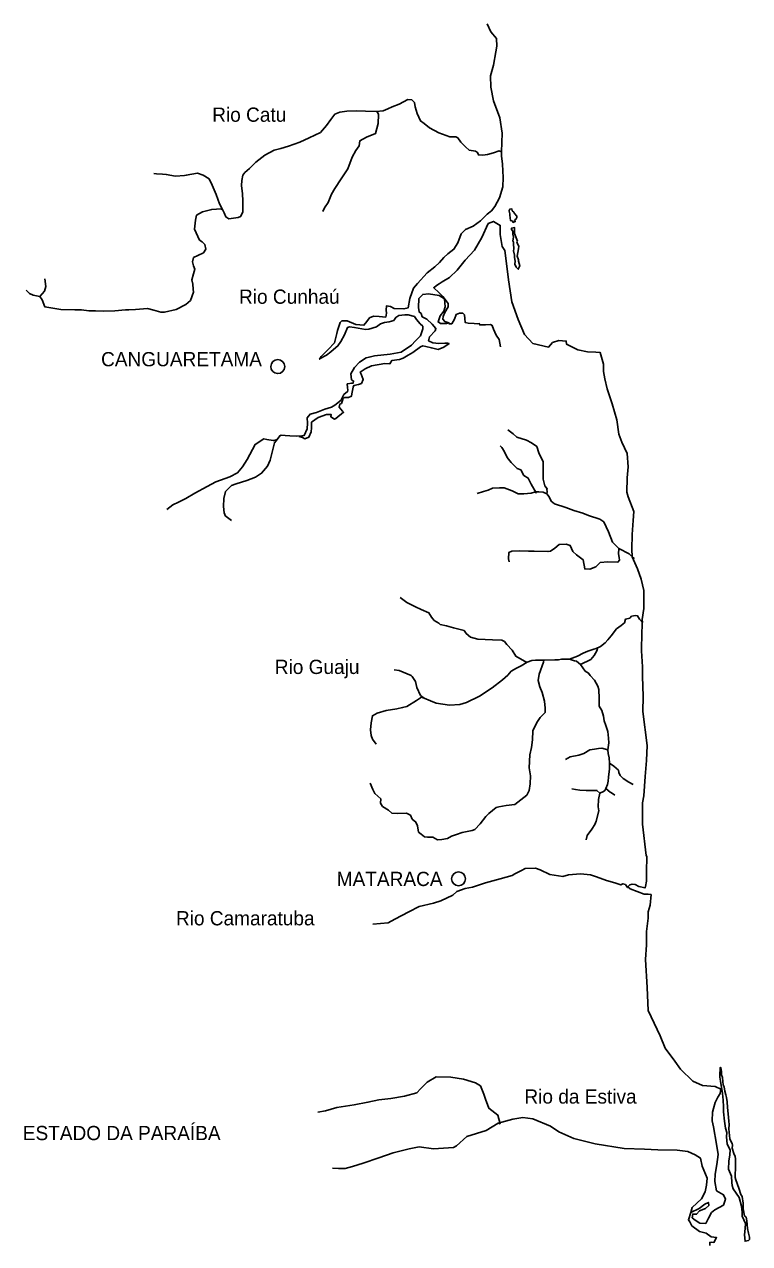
# Model space of a CAD drawing. Extents: x 662444 to 1640468, y 7452018 to 9606170.
# Drawn here: x 1584655 to 1619732, y 9241680 to 9300665 of the extents above; entities that cross this region are included whole.
import ezdxf

# ---------------------------------------------------------------- set-up
doc = ezdxf.new("R2010")
doc.units = 0
for name, color, linetype in [('Level 1', 7, 'Continuous'), ('Level 2', 7, 'Continuous'), ('Level 3', 7, 'Continuous')]:
    doc.layers.add(name, color=color, linetype=linetype)

msp = doc.modelspace()

# ---------------------------------------------------------------- linework, layer by layer
at = {"layer": 'Level 1'}
for points in [[(1607340, 9298700), (1607454, 9299341), (1607511, 9299617), (1607497, 9299976), (1607214, 9300309), (1607039, 9300696)], [(1599983, 9282492), (1600026, 9282597), (1600111, 9282757), (1600286, 9282899), (1600304, 9282964), (1600275, 9283095), (1600272, 9283275), (1600304, 9283282), (1600476, 9283302), (1600564, 9283308), (1600575, 9283406), (1600480, 9283474), (1600439, 9283752), (1600618, 9284072), (1600868, 9284327), (1601182, 9284531), (1601329, 9284568), (1601590, 9284626), (1602347, 9284712), (1602876, 9284813), (1603379, 9285150), (1603579, 9285349), (1603806, 9285604), (1603920, 9285935), (1603931, 9286058), (1603798, 9286175), (1603626, 9286391), (1603516, 9286540), (1603218, 9286606), (1603064, 9286610), (1602764, 9286584), (1602622, 9286490), (1602522, 9286337), (1602293, 9286270), (1602065, 9286244), (1601877, 9286184), (1601686, 9286026), (1601310, 9285913), (1601148, 9285908), (1600623, 9285996), (1600381, 9286026), (1600283, 9286005), (1600136, 9285650), (1599957, 9285328), (1599821, 9285111), (1599613, 9284929), (1599472, 9284828), (1599266, 9284670), (1598962, 9284499), (1598936, 9284466), (1599004, 9284595), (1599354, 9284944), (1599655, 9285263), (1599773, 9285716), (1599801, 9285862), (1599934, 9286249), (1600016, 9286321), (1600260, 9286331), (1600685, 9286149), (1601080, 9286106), (1601224, 9286297), (1601350, 9286466), (1601547, 9286543), (1601822, 9286535), (1602129, 9286503), (1602167, 9286698), (1602154, 9286844), (1602168, 9287048), (1602362, 9287011), (1602545, 9286916), (1603015, 9286896), (1603220, 9286956), (1603297, 9287402), (1603473, 9287903), (1603666, 9288135), (1604134, 9288644), (1604515, 9288935), (1604731, 9289142), (1604940, 9289381), (1605132, 9289563), (1605430, 9289784), (1605625, 9290089), (1605783, 9290525), (1605992, 9290748), (1606353, 9290909), (1606716, 9291169), (1607041, 9291478), (1607241, 9291645), (1607409, 9291861), (1607640, 9292270), (1607791, 9292804), (1607813, 9293260), (1607774, 9293905), (1607728, 9294306), (1607725, 9294501), (1607758, 9295405), (1607658, 9296141), (1607348, 9296963), (1607213, 9297636), (1607204, 9298174), (1607340, 9298700)], [(1607725, 9294501), (1607614, 9294553), (1607343, 9294446), (1607049, 9294364), (1606829, 9294345), (1606619, 9294350), (1606573, 9294473), (1606478, 9294533), (1606171, 9294574), (1605989, 9294741), (1605769, 9294967), (1605612, 9295183), (1605524, 9295226), (1605234, 9295233), (1604695, 9295418), (1604256, 9295666), (1603995, 9295868), (1603812, 9295994), (1603659, 9296357), (1603554, 9296669), (1603520, 9296891), (1603394, 9297023), (1603208, 9297028), (1602780, 9296803), (1602444, 9296673), (1602230, 9296573), (1602002, 9296489), (1601668, 9296457), (1601158, 9296469), (1600697, 9296481), (1600251, 9296468), (1599916, 9296412), (1599678, 9296328), (1599469, 9296065), (1599266, 9295776), (1598973, 9295441), (1598423, 9295170), (1597979, 9294970), (1597423, 9294779), (1597055, 9294659), (1596729, 9294585), (1596285, 9294344), (1595845, 9293997), (1595545, 9293686), (1595322, 9293505), (1595221, 9293377), (1595173, 9293118), (1595158, 9292873), (1595212, 9292473), (1595227, 9292130), (1595228, 9291870), (1595220, 9291585), (1595109, 9291367), (1595002, 9291329), (1594538, 9291252), (1594404, 9291353), (1594320, 9291543), (1594251, 9291682), (1594097, 9291988), (1593923, 9292432), (1593732, 9292885), (1593587, 9293191), (1593308, 9293369), (1593027, 9293465), (1592482, 9293365), (1592392, 9293351), (1591970, 9293329), (1591518, 9293406), (1591332, 9293411), (1591050, 9293434), (1590912, 9293454)], [(1601668, 9296457), (1601717, 9296455), (1601777, 9296307), (1601773, 9295875), (1601630, 9295381), (1601204, 9295213), (1600883, 9295034), (1600852, 9294782), (1600691, 9294558), (1600504, 9294237), (1600295, 9293680), (1599973, 9293191), (1599668, 9292719), (1599515, 9292454), (1599350, 9292050), (1599164, 9291786), (1599094, 9291617)], [(1594251, 9291682), (1594171, 9291742), (1593717, 9291713), (1593268, 9291593), (1592979, 9291429), (1592932, 9291195), (1592888, 9290756), (1593125, 9290228), (1593260, 9290152), (1593378, 9290010), (1593429, 9289797), (1593310, 9289621), (1593039, 9289489), (1592841, 9289380), (1592787, 9289178), (1592831, 9288982), (1592891, 9288817), (1592827, 9288590), (1592755, 9288308), (1592806, 9288094), (1592816, 9287858), (1592827, 9287710), (1592687, 9287315), (1592462, 9287109), (1592002, 9286868), (1591424, 9286744), (1591253, 9286749), (1590908, 9286847), (1590610, 9286928), (1590033, 9286870), (1589709, 9286854), (1589539, 9286858), (1589035, 9286814), (1588468, 9286786), (1588095, 9286805), (1587771, 9286813), (1587424, 9286855), (1587093, 9286863), (1586421, 9286879), (1585639, 9287005), (1585519, 9287342), (1585409, 9287508), (1585087, 9287566), (1584903, 9287651), (1584737, 9287810)], [(1608127, 9291443), (1608129, 9291508), (1608108, 9291630), (1608101, 9291663), (1608134, 9291720), (1608233, 9291741), (1608254, 9291651), (1608333, 9291576), (1608356, 9291510), (1608466, 9291386), (1608471, 9291319), (1608446, 9291255), (1608379, 9291208), (1608394, 9291127), (1608287, 9291088), (1608281, 9291146), (1608160, 9291180), (1608127, 9291443)], [(1618130, 9246499), (1617993, 9247327), (1617920, 9247621), (1617932, 9248045), (1617987, 9248223), (1618068, 9248514), (1618197, 9248764), (1618315, 9248948), (1618346, 9249151), (1618058, 9249281), (1617459, 9249330), (1616980, 9249546), (1616397, 9250125), (1616116, 9250507), (1615649, 9251132), (1615406, 9251733), (1614819, 9252964), (1614778, 9254074), (1614696, 9255420), (1614749, 9256129), (1614743, 9256772), (1614827, 9257423), (1614820, 9257733), (1614926, 9258056), (1614965, 9258569), (1614820, 9258581), (1614698, 9258584), (1614634, 9258586), (1613952, 9258840), (1613849, 9258933), (1613941, 9259044), (1614056, 9259073), (1614201, 9259061), (1614376, 9258959), (1614675, 9258886), (1614693, 9258959), (1614741, 9259210), (1614745, 9259667), (1614767, 9260408), (1614736, 9260457), (1614545, 9261979), (1614558, 9262998), (1614617, 9263338), (1614676, 9264283), (1614739, 9265047), (1614784, 9265771), (1614563, 9267424), (1614585, 9268149), (1614548, 9269137), (1614553, 9269584), (1614510, 9270361), (1614511, 9271265), (1614528, 9271551), (1614537, 9271876), (1614617, 9272412), (1614610, 9273276), (1614479, 9273826), (1614307, 9274319), (1614056, 9274905), (1614042, 9275280), (1614055, 9275989), (1614106, 9276656), (1614134, 9277104), (1613863, 9277812), (1613789, 9278042), (1613808, 9278727), (1613856, 9279255), (1613809, 9279900), (1613549, 9280453), (1613414, 9280848), (1613312, 9281528), (1613090, 9282308), (1612844, 9283039), (1612728, 9283523), (1612665, 9283876), (1612659, 9284234), (1612505, 9284785), (1612302, 9284806), (1611896, 9284817), (1611421, 9284918), (1610878, 9285194), (1610865, 9285340), (1610510, 9285374), (1610199, 9285268), (1609998, 9285045), (1609249, 9285228), (1608849, 9285661), (1608537, 9286395), (1608236, 9287242), (1608064, 9288314), (1607973, 9289100), (1607885, 9289721), (1607768, 9289920), (1607663, 9290493), (1607667, 9290941), (1607508, 9291035), (1607340, 9291137), (1607093, 9291029), (1606775, 9290361), (1606418, 9289750), (1605967, 9289265)], [(1608513, 9290178), (1608480, 9290146), (1608510, 9290047), (1608572, 9289931), (1608559, 9289810), (1608514, 9289623), (1608492, 9289444), (1608553, 9289280), (1608551, 9289215), (1608625, 9288977), (1608540, 9288816), (1608437, 9288917), (1608376, 9289065), (1608389, 9289203), (1608361, 9289383), (1608364, 9289497), (1608313, 9289710), (1608324, 9289808), (1608306, 9290044), (1608317, 9290133), (1608278, 9290191), (1608308, 9290378), (1608287, 9290509), (1608283, 9290656), (1608213, 9290747), (1608214, 9290804), (1608361, 9290833), (1608358, 9290735), (1608353, 9290548), (1608513, 9290178)], [(1605967, 9289265), (1605589, 9288778), (1605213, 9288412), (1604867, 9288217), (1604719, 9288115), (1604595, 9288037), (1604454, 9287926), (1604698, 9287692), (1604896, 9287499), (1605052, 9287284), (1605154, 9287166), (1605150, 9286996), (1604987, 9286723), (1604917, 9286529), (1604898, 9286399), (1604983, 9286291), (1605177, 9286229), (1605078, 9286190), (1604786, 9286198), (1604668, 9286275), (1604772, 9286558), (1604941, 9286789), (1605004, 9287008), (1604975, 9287391), (1604719, 9287553), (1604203, 9287624), (1603926, 9287605), (1603734, 9287399), (1603714, 9286975), (1603748, 9286755), (1603852, 9286671), (1603896, 9286523), (1604112, 9286411), (1604372, 9286160), (1604561, 9285951), (1604518, 9285839), (1604241, 9285544), (1604204, 9285358), (1604404, 9285255), (1604694, 9285222), (1604987, 9285239), (1605133, 9285236), (1605198, 9285234), (1604941, 9285054), (1604671, 9284930), (1604340, 9285011), (1604066, 9285084), (1603922, 9285113), (1603806, 9285067), (1603443, 9284799), (1603213, 9284666), (1602981, 9284525), (1602793, 9284457), (1602435, 9284409), (1602333, 9284248), (1602083, 9284255), (1601440, 9284150), (1601144, 9284002), (1600896, 9283845), (1600950, 9283738), (1601048, 9283491), (1600954, 9283298), (1600815, 9283245), (1600594, 9283201), (1600552, 9283113), (1600494, 9282797), (1600483, 9282682), (1600326, 9282614), (1600148, 9282618), (1600074, 9282587), (1600064, 9282514), (1599986, 9282328), (1599905, 9282290), (1599894, 9282234), (1599884, 9282144), (1600049, 9281960), (1600096, 9281902), (1599723, 9281594), (1599657, 9281572), (1599482, 9281674), (1599485, 9281796), (1599404, 9281798), (1599274, 9281784), (1598857, 9281641), (1598543, 9281421), (1598543, 9281152), (1598530, 9280948), (1598417, 9280690), (1598221, 9280622), (1598100, 9280674), (1597948, 9280735), (1598192, 9280778), (1598339, 9281100), (1598355, 9281377), (1598338, 9281638), (1598473, 9281806), (1598791, 9281895), (1599185, 9282048), (1599503, 9282154), (1599668, 9282247), (1599983, 9282492)], [(1585409, 9287508), (1585635, 9287763), (1585698, 9287989), (1585636, 9288357)], [(1605177, 9286229), (1605199, 9286180), (1605329, 9286176), (1605457, 9286410), (1605536, 9286627), (1605700, 9286688), (1605863, 9286692), (1605949, 9286609), (1605952, 9286429), (1605971, 9286249), (1606124, 9286205), (1606416, 9286189), (1606554, 9286185), (1606659, 9286191), (1606674, 9286158), (1606682, 9286125), (1606957, 9286135), (1607201, 9286144), (1607281, 9286101), (1607340, 9285913), (1607478, 9285624), (1607626, 9285425), (1607681, 9285064)], [(1598192, 9280778), (1598071, 9280764), (1597803, 9280747), (1597487, 9280755), (1597260, 9280778), (1597074, 9280790), (1597009, 9280759), (1596875, 9280583), (1596756, 9280416), (1596667, 9280092), (1596539, 9279582), (1596417, 9279292), (1596131, 9278949), (1595827, 9278761), (1595409, 9278593), (1594903, 9278442), (1594673, 9278359), (1594390, 9278065), (1594307, 9277725), (1594280, 9277335), (1594321, 9277040), (1594388, 9276876), (1594420, 9276851), (1594675, 9276664)], [(1609927, 9277947), (1609948, 9278061), (1609926, 9278159), (1609943, 9278191), (1609825, 9278333), (1609745, 9278661), (1609745, 9278931), (1609751, 9279151), (1609745, 9279501), (1609539, 9279938), (1609434, 9280242), (1609188, 9280420), (1608940, 9280548), (1608473, 9280691), (1608300, 9280858), (1608038, 9281045)], [(1596875, 9280583), (1596792, 9280553), (1596727, 9280539), (1596695, 9280540), (1596389, 9280588), (1596236, 9280616), (1595815, 9280342), (1595429, 9279610), (1595209, 9279258), (1594958, 9278963), (1594596, 9278776), (1593917, 9278533), (1593489, 9278316), (1592897, 9277981), (1592469, 9277723), (1592107, 9277545), (1591829, 9277422), (1591546, 9277193)], [(1609371, 9278043), (1609403, 9278002), (1609171, 9278415), (1609026, 9278712), (1608819, 9278848), (1608665, 9279114), (1608487, 9279175), (1608195, 9279467), (1608000, 9279717), (1607863, 9280014), (1607746, 9280197), (1607660, 9280273)], [(1614056, 9274905), (1614143, 9274829), (1613914, 9275056), (1613411, 9275305), (1613104, 9275614), (1612900, 9276117), (1612678, 9276604), (1612487, 9276723), (1611941, 9276908), (1611669, 9277021), (1611227, 9277147), (1610850, 9277288), (1610287, 9277473), (1610128, 9277592), (1610029, 9277815), (1609927, 9277947), (1609752, 9278034), (1609542, 9278056), (1609371, 9278043), (1609159, 9277984), (1608810, 9277960), (1608542, 9277959), (1608255, 9278097), (1607861, 9278238), (1607635, 9278252), (1607302, 9278220), (1607080, 9278136), (1606860, 9278060), (1606549, 9277962)], [(1613411, 9275305), (1613402, 9275297), (1613396, 9275053), (1613423, 9274880), (1613436, 9274750), (1613360, 9274654), (1612874, 9274659), (1612508, 9274628), (1612300, 9274429), (1611997, 9274315), (1611762, 9274321), (1611677, 9274763), (1611351, 9275000), (1611178, 9275160), (1611057, 9275448), (1610856, 9275526), (1610515, 9275503), (1610316, 9275329), (1610101, 9275180), (1609979, 9275159), (1609307, 9275176), (1609040, 9275183), (1608618, 9275202), (1608237, 9275188), (1608080, 9275110), (1608064, 9274817), (1608101, 9274662)], [(1608975, 9269805), (1608950, 9269790), (1608424, 9270096), (1608255, 9270386), (1607986, 9270662), (1607869, 9270812), (1607749, 9270881), (1607296, 9270892), (1606585, 9270928), (1606239, 9271026), (1606025, 9271203), (1605924, 9271336), (1605417, 9271472), (1605071, 9271570), (1604766, 9271635), (1604702, 9271701), (1604478, 9271822), (1604346, 9271980), (1604222, 9272196), (1603854, 9272351), (1603574, 9272481), (1603159, 9272704), (1602833, 9272941)], [(1614537, 9271876), (1614550, 9271729), (1614400, 9271896), (1614316, 9272045), (1614210, 9272064), (1614023, 9272028), (1613932, 9271941), (1613735, 9271897), (1613673, 9271719), (1613524, 9271584), (1613292, 9271419), (1613032, 9271084), (1612872, 9270884), (1612738, 9270749), (1612522, 9270576), (1612309, 9270476), (1612203, 9270445), (1611908, 9270339), (1611678, 9270247), (1611407, 9270100), (1611022, 9269963)], [(1612309, 9270476), (1612383, 9270506), (1612382, 9270473), (1612338, 9270361), (1612218, 9270135), (1612050, 9269937), (1611558, 9269705)], [(1609782, 9269907), (1609762, 9269817), (1609550, 9269235), (1609501, 9268928), (1609581, 9268615), (1609695, 9268343), (1609814, 9267925), (1609844, 9267590), (1609837, 9267377), (1609605, 9267140), (1609444, 9266891), (1609245, 9266480), (1609233, 9266057), (1609181, 9265683), (1609107, 9265327), (1609072, 9264692), (1609134, 9264307), (1609122, 9263916), (1609074, 9263607), (1608953, 9263374), (1608374, 9262926), (1607951, 9262871), (1607608, 9262815), (1607478, 9262777), (1607113, 9262494), (1606971, 9262343), (1606694, 9261992), (1606434, 9261713), (1606320, 9261667), (1605823, 9261575), (1605553, 9261476), (1605308, 9261392), (1605126, 9261276), (1604841, 9261225), (1604629, 9261215), (1604415, 9261343), (1604147, 9261350), (1604003, 9261362), (1603844, 9261488), (1603718, 9261589), (1603661, 9261884), (1603594, 9262073), (1603411, 9262217), (1603328, 9262406), (1603136, 9262510), (1602690, 9262496), (1602431, 9262504), (1602273, 9262646), (1601978, 9262833), (1601886, 9262991), (1601892, 9263203), (1601600, 9263454), (1601516, 9263652), (1601387, 9263957)], [(1602540, 9269436), (1602782, 9269413), (1603358, 9269170), (1603413, 9269112), (1603577, 9268871), (1603642, 9268592), (1603808, 9268205), (1603991, 9268070), (1604296, 9267932), (1604568, 9267826), (1605213, 9267736), (1605717, 9267763), (1606035, 9267861), (1606660, 9268163), (1607287, 9268570), (1607776, 9268957), (1608033, 9269178), (1608201, 9269369), (1608456, 9269517), (1608687, 9269625), (1608975, 9269805), (1609205, 9269889), (1609375, 9269909), (1609780, 9269907), (1610316, 9269916), (1610486, 9269928), (1610641, 9269949), (1611022, 9269963), (1611263, 9269867), (1611351, 9269865), (1611558, 9269705), (1611783, 9269373), (1611943, 9269279), (1612028, 9269162), (1612224, 9268945), (1612395, 9268655), (1612447, 9268492), (1612450, 9268059), (1612456, 9267675), (1612580, 9267468), (1612661, 9267205), (1612704, 9266976), (1612770, 9266754), (1612874, 9266450), (1612906, 9266139), (1612924, 9265911), (1612882, 9265562), (1612884, 9265390), (1612935, 9265177), (1612960, 9264924), (1612952, 9264646), (1612908, 9264240), (1612895, 9264045), (1612857, 9263890), (1612771, 9263698), (1612736, 9263601), (1612662, 9263545), (1612482, 9263477), (1612424, 9263160), (1612413, 9262818), (1612441, 9262622), (1612304, 9262112), (1612243, 9261958), (1612107, 9261734), (1611879, 9261422), (1611824, 9261220)], [(1603991, 9268070), (1603870, 9268118), (1603615, 9267948), (1603145, 9267668), (1602949, 9267616), (1602673, 9267557), (1602159, 9267473), (1601710, 9267339), (1601487, 9267214), (1601429, 9266873), (1601403, 9266532), (1601420, 9266270), (1601489, 9266089), (1601668, 9265849)], [(1610826, 9265102), (1611056, 9265227), (1611464, 9265305), (1611710, 9265389), (1611998, 9265568), (1612235, 9265603), (1612430, 9265638), (1612592, 9265651), (1612882, 9265562)], [(1614098, 9263899), (1613898, 9264002), (1613620, 9264188), (1613478, 9264330), (1613401, 9264480), (1613396, 9264578), (1613167, 9264779), (1612960, 9264924)], [(1611126, 9263676), (1611303, 9263647), (1611513, 9263617), (1611828, 9263600), (1612063, 9263602), (1612257, 9263605), (1612347, 9263603), (1612482, 9263477)], [(1613207, 9263368), (1613057, 9263495), (1612993, 9263521), (1612771, 9263698)], [(1613849, 9258933), (1613832, 9258901), (1613722, 9259050), (1613602, 9259086), (1613503, 9259032), (1613214, 9259129), (1612805, 9259246), (1612332, 9259429), (1612035, 9259528), (1611550, 9259564), (1610966, 9259514), (1610696, 9259448), (1610067, 9259530), (1609596, 9259771), (1609370, 9259851), (1608884, 9259830), (1608695, 9259738), (1608382, 9259567), (1608242, 9259489), (1607663, 9259333), (1606960, 9259132), (1606322, 9258920), (1605972, 9258864), (1605579, 9258712), (1605371, 9258539), (1604797, 9258269), (1604444, 9258148), (1603744, 9257995), (1603242, 9257731), (1602576, 9257382), (1602254, 9257203), (1601516, 9257133)], [(1619315, 9244053), (1619367, 9243954), (1619424, 9243643), (1619423, 9243358), (1619478, 9243030), (1619558, 9242954), (1619601, 9242782), (1619631, 9242415), (1619681, 9242193), (1619732, 9241996), (1619728, 9241882), (1619678, 9241825), (1619516, 9241797), (1619484, 9242100), (1619509, 9242417), (1619532, 9242654), (1619456, 9242835), (1619372, 9243000), (1619379, 9243196), (1619347, 9243499), (1619221, 9243918), (1618942, 9244332), (1618881, 9244489), (1618870, 9244636), (1618854, 9244946), (1618718, 9245285), (1618730, 9245668), (1618771, 9245968), (1618786, 9246212), (1618640, 9246486), (1618618, 9246844), (1618625, 9247049), (1618566, 9247270), (1618519, 9247606), (1618476, 9248063), (1618474, 9248299), (1618460, 9248626), (1618428, 9248945), (1618325, 9249535), (1618290, 9249739), (1618294, 9249903), (1618300, 9250081), (1618303, 9250188), (1618336, 9250203), (1618370, 9249990), (1618374, 9249843), (1618427, 9249720), (1618438, 9249516), (1618449, 9249360), (1618494, 9249269), (1618537, 9249056), (1618588, 9248875), (1618609, 9248744), (1618643, 9248539), (1618660, 9248262), (1618699, 9247951), (1618729, 9247600), (1618742, 9247445), (1618735, 9247233), (1618778, 9246750), (1618862, 9246577), (1618892, 9246519), (1618898, 9246446), (1618894, 9246291), (1618975, 9246044), (1619036, 9245888), (1619049, 9245789), (1619055, 9245455), (1619039, 9244876), (1619068, 9244761), (1619218, 9244358), (1619315, 9244053)], [(1607571, 9247501), (1607659, 9247475), (1607550, 9247901), (1607122, 9248230), (1606965, 9248667), (1606884, 9248913), (1606717, 9249309), (1606477, 9249454), (1605892, 9249640), (1605287, 9249738), (1604574, 9249741), (1604138, 9249492), (1603821, 9249174), (1603629, 9248976), (1603034, 9248812), (1602382, 9248708), (1601805, 9248642), (1601267, 9248517), (1600599, 9248389), (1599762, 9248265), (1599214, 9248108), (1598856, 9248036)], [(1616883, 9243182), (1616954, 9243433), (1617412, 9243844), (1617584, 9244182), (1617650, 9244514), (1617676, 9244848), (1617435, 9245434), (1617356, 9245818), (1617103, 9245981), (1616742, 9246137), (1616234, 9246208), (1615295, 9246225), (1614648, 9246251), (1613660, 9246286), (1612264, 9246502), (1611236, 9246759), (1610508, 9247096), (1610095, 9247369), (1609247, 9247717), (1608770, 9247787), (1608282, 9247702), (1607571, 9247501), (1606994, 9247158), (1606054, 9246857), (1605555, 9246406), (1605407, 9246337), (1604441, 9246265), (1603756, 9246365), (1603267, 9246264), (1602492, 9246072), (1601796, 9245823), (1601036, 9245565), (1600521, 9245417), (1600170, 9245319), (1599854, 9245312), (1599564, 9245336)], [(1617807, 9241584), (1617804, 9241739), (1617901, 9241744), (1618007, 9241741), (1618135, 9241974), (1617876, 9242006), (1617631, 9242184), (1617310, 9242273), (1616945, 9242544), (1616844, 9242727), (1616774, 9242826), (1616883, 9243182), (1617286, 9243383), (1617567, 9243595), (1617739, 9243673), (1617759, 9243525), (1617593, 9243375), (1617314, 9243260), (1617164, 9243101), (1616978, 9243106), (1616948, 9242928), (1617099, 9242817), (1617321, 9242673), (1617611, 9242649), (1617749, 9242905), (1617886, 9243179), (1618045, 9243314), (1618473, 9243546), (1618562, 9243829), (1618471, 9244044), (1618136, 9244240), (1618045, 9244684), (1618071, 9245033), (1618141, 9245512), (1618212, 9245999), (1618130, 9246499)]]:
    msp.add_lwpolyline(points, dxfattribs=at)
at = {"layer": 'Level 2'}
for centre, major_axis in [((1596909, 9284111), (337, -4)), ((1605653, 9259330), (336, -4))]:
    msp.add_ellipse(centre, major_axis=major_axis, ratio=0.999999, dxfattribs=at)

# ---------------------------------------------------------------- texts
at = {"layer": 'Level 3'}
for s, height, p in [('Rio Catu', 689.1, (1593738, 9295954)), ('Rio Cunhaú', 689, (1595036, 9287148)), ('CANGUARETAMA', 688.86, (1588364, 9284124)), ('Rio Guaju', 688.8, (1596767, 9269238)), ('MATARACA', 688.8, (1599762, 9258980)), ('Rio Camaratuba', 688.61, (1591986, 9257077)), ('Rio da Estiva', 688.82, (1608840, 9248453)), ('ESTADO DA PARAÍBA', 688.37, (1584579, 9246686))]:
    msp.add_text(s, height=height, dxfattribs=at).set_placement(p)

doc.saveas('drawing.dxf')
